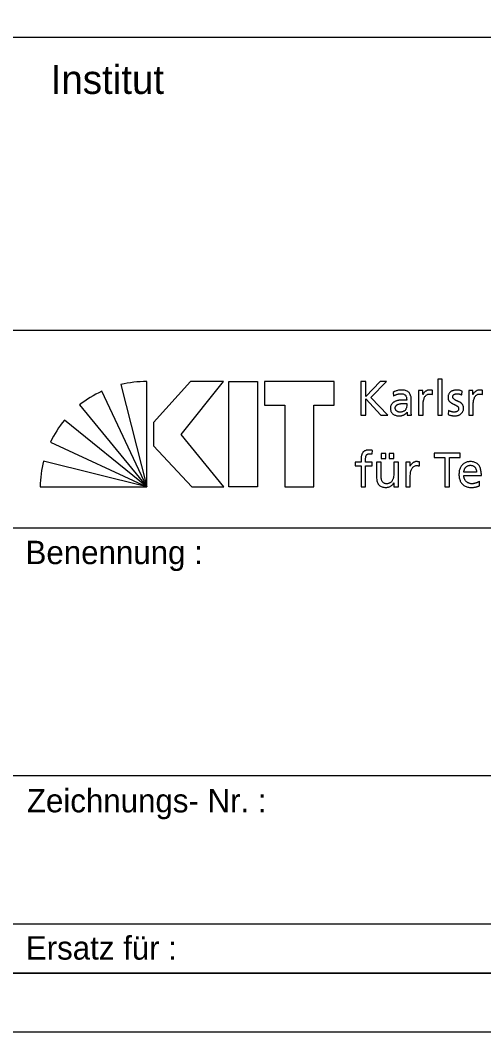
# Model space of a CAD drawing. Extents: x 0 to 841, y 0 to 594.
# Drawn here: x 752.7 to 792.3, y 0 to 86.5 of the extents above; entities that cross this region are included whole.
import ezdxf

# ---------------------------------------------------------------- set-up
doc = ezdxf.new("R2010")
doc.units = 0
doc.layers.add('90_Plankopf', color=7, linetype='Continuous')

msp = doc.modelspace()

# ---------------------------------------------------------------- linework, layer by layer
at = {"layer": '90_Plankopf'}
for p, q in [((836, 84.99), (658.12, 84.99)), ((658.12, 59.99), (836, 59.99)), ((658.12, 59.99), (836, 59.99)), ((763.481, 46.586), (763.481, 55.584)), ((781.81, 55.586), (781.81, 52.706)), ((763.481, 46.586), (759.633, 54.752)), ((761.275, 55.333), (763.481, 46.586)), ((784.579, 54.662), (784.6, 54.332)), ((787.926, 54.484), (787.926, 54.831)), ((790.457, 54.439), (790.49, 54.778)), ((792.211, 54.484), (792.211, 54.831)), ((785.73, 53.709), (785.73, 53.523)), ((786.118, 53.118), (786.118, 53.989)), ((757.744, 53.585), (763.481, 46.586)), ((789.297, 53.118), (789.277, 52.772)), ((763.481, 46.586), (756.434, 52.286)), ((781.81, 52.706), (782.222, 52.706)), ((783.506, 52.706), (784.108, 52.706)), ((755.24, 50.413), (763.481, 46.586)), ((782.773, 49.393), (782.79, 49.706)), ((763.481, 46.586), (754.658, 48.788)), ((786.827, 48.365), (786.827, 48.712)), ((791.706, 47.841), (790.616, 47.841)), ((790.616, 47.552), (792.119, 47.552)), ((791.958, 46.673), (791.958, 47.061)), ((754.364, 46.586), (763.481, 46.586)), ((752.001, 43.07), (836, 43.07)), ((752.001, 21.92), (836, 21.92)), ((752.001, 9.23), (836, 9.23)), ((836, 5), (658.12, 5)), ((669.8, 5), (836, 5)), ((669.8, 5), (836, 5))]:
    msp.add_line(p, q, dxfattribs=at)
for points in [[(0, 0), (841, 0), (841, 594), (0, 594)], [(25, 589), (836, 589), (836, 5), (25, 5)], [(770.066, 55.586), (767.236, 55.586), (764.073, 52.099), (764.073, 50.092), (767.338, 46.586), (770.085, 46.586), (766.422, 51.063)], [(772.97, 55.586), (772.97, 46.586), (770.501, 46.586), (770.501, 55.586)], [(773.562, 55.586), (773.562, 53.56), (775.301, 53.56), (775.301, 46.586), (777.771, 46.586), (777.771, 53.56), (779.51, 53.56), (779.51, 55.586)]]:
    msp.add_lwpolyline(points, close=True, dxfattribs=at)
for points in [[(784.108, 52.706), (782.647, 54.224), (784.001, 55.586), (783.452, 55.586), (782.222, 54.319), (782.222, 55.586), (781.81, 55.586)], [(788.381, 52.706), (788.768, 52.706), (788.768, 55.801), (788.381, 55.801), (788.381, 52.706)], [(787.122, 54.484), (787.113, 54.484), (787.113, 54.81), (786.75, 54.81), (786.75, 52.706), (787.138, 52.706), (787.138, 53.663)], [(791.407, 54.484), (791.398, 54.484), (791.398, 54.81), (791.035, 54.81), (791.035, 52.706), (791.423, 52.706), (791.423, 53.663)], [(782.222, 52.706), (782.222, 54.117), (783.506, 52.706)], [(785.763, 52.978), (785.772, 52.978), (785.772, 52.706), (786.135, 52.706)], [(783.554, 49.426), (783.554, 49.013), (783.942, 49.013), (783.942, 49.426), (783.554, 49.426)], [(784.231, 49.426), (784.231, 49.013), (784.619, 49.013), (784.619, 49.426), (784.231, 49.426)], [(788.99, 46.586), (789.403, 46.586), (789.403, 49.104), (790.298, 49.104), (790.298, 49.467), (788.094, 49.467), (788.094, 49.104), (788.99, 49.104), (788.99, 46.586)], [(781.824, 48.885), (781.824, 48.691), (781.329, 48.691), (781.329, 48.378), (781.824, 48.378), (781.824, 46.586), (782.212, 46.586), (782.212, 48.378), (782.769, 48.378), (782.769, 48.691), (782.212, 48.691), (782.212, 48.918)], [(783.542, 47.602), (783.542, 48.691), (783.154, 48.691), (783.154, 47.441)], [(785.015, 46.586), (785.015, 48.691), (784.627, 48.691), (784.627, 47.717)], [(786.022, 48.365), (786.014, 48.365), (786.014, 48.691), (785.651, 48.691), (785.651, 46.586), (786.039, 46.586), (786.039, 47.544)], [(784.631, 46.921), (784.639, 46.921), (784.639, 46.586), (785.015, 46.586)]]:
    msp.add_lwpolyline(points, dxfattribs=at)
for centre, start, end in [((763.449, 46.056), 89.80527, 103.18947), ((763.662, 46.118), 115.01261, 128.3968), ((763.816, 46.263), 140.78977, 154.17397), ((763.891, 46.438), 165.72225, 179.10644)]:
    msp.add_arc(centre, 9.528, start, end, dxfattribs=at)
for points in [[(786.118, 53.989), (786.119, 54.18), (786.091, 54.341), (786.033, 54.47), (785.975, 54.599), (785.884, 54.696), (785.759, 54.762), (785.635, 54.827), (785.472, 54.86), (785.272, 54.86), (785.138, 54.859), (785.014, 54.841), (784.898, 54.804), (784.782, 54.768), (784.676, 54.721), (784.579, 54.662)], [(784.6, 54.332), (784.653, 54.376), (784.713, 54.414), (784.779, 54.446), (784.846, 54.478), (784.916, 54.503), (784.99, 54.52), (785.063, 54.538), (785.137, 54.546), (785.21, 54.546), (785.339, 54.546), (785.441, 54.526), (785.518, 54.485), (785.594, 54.444), (785.649, 54.383), (785.682, 54.302), (785.715, 54.219), (785.731, 54.118), (785.73, 53.997)], [(787.926, 54.831), (787.899, 54.837), (787.873, 54.841), (787.849, 54.846), (787.824, 54.85), (787.798, 54.854), (787.769, 54.856), (787.741, 54.859), (787.708, 54.86), (787.67, 54.86), (787.595, 54.859), (787.523, 54.843), (787.452, 54.811), (787.382, 54.779), (787.318, 54.736), (787.261, 54.679), (787.203, 54.623), (787.157, 54.558), (787.122, 54.484)], [(787.138, 53.663), (787.139, 53.84), (787.163, 53.993), (787.21, 54.121), (787.257, 54.249), (787.323, 54.348), (787.409, 54.416), (787.494, 54.486), (787.595, 54.521), (787.712, 54.521), (787.746, 54.522), (787.78, 54.519), (787.818, 54.514), (787.855, 54.509), (787.891, 54.499), (787.926, 54.484)], [(790.49, 54.778), (790.414, 54.801), (790.337, 54.82), (790.259, 54.836), (790.181, 54.851), (790.097, 54.859), (790.007, 54.86), (789.903, 54.86), (789.805, 54.847), (789.716, 54.82), (789.625, 54.794), (789.547, 54.753), (789.48, 54.7), (789.412, 54.647), (789.359, 54.579), (789.322, 54.498), (789.284, 54.417), (789.265, 54.321), (789.264, 54.212), (789.265, 54.128), (789.282, 54.056), (789.315, 53.994), (789.347, 53.933), (789.391, 53.88), (789.445, 53.834), (789.5, 53.79), (789.559, 53.75), (789.623, 53.715), (789.688, 53.68), (789.753, 53.647), (789.817, 53.617), (789.882, 53.586), (789.942, 53.555), (789.995, 53.522), (790.05, 53.49), (790.093, 53.454), (790.126, 53.413), (790.158, 53.373), (790.176, 53.325), (790.176, 53.271), (790.176, 53.215), (790.163, 53.167), (790.139, 53.128), (790.116, 53.09), (790.084, 53.059), (790.045, 53.035), (790.006, 53.012), (789.963, 52.995), (789.917, 52.985), (789.871, 52.975), (789.825, 52.97), (789.78, 52.97), (789.742, 52.97), (789.695, 52.975), (789.639, 52.986), (789.584, 52.997), (789.526, 53.014), (789.466, 53.036), (789.405, 53.058), (789.35, 53.085), (789.297, 53.118)], [(789.277, 52.772), (789.366, 52.726), (789.46, 52.694), (789.558, 52.678), (789.656, 52.662), (789.755, 52.655), (789.854, 52.656), (789.949, 52.656), (790.04, 52.669), (790.127, 52.695), (790.215, 52.722), (790.293, 52.762), (790.363, 52.816), (790.431, 52.869), (790.487, 52.938), (790.527, 53.02), (790.568, 53.103), (790.588, 53.2), (790.589, 53.312), (790.588, 53.408), (790.571, 53.489), (790.539, 53.556), (790.506, 53.622), (790.462, 53.679), (790.408, 53.726), (790.354, 53.772), (790.295, 53.811), (790.23, 53.845), (790.165, 53.878), (790.101, 53.909), (790.036, 53.937), (789.971, 53.966), (789.912, 53.995), (789.858, 54.026), (789.804, 54.058), (789.76, 54.095), (789.727, 54.136), (789.695, 54.179), (789.678, 54.23), (789.677, 54.291), (789.678, 54.348), (789.696, 54.396), (789.729, 54.434), (789.763, 54.472), (789.808, 54.5), (789.864, 54.519), (789.92, 54.538), (789.982, 54.546), (790.048, 54.546), (790.072, 54.546), (790.102, 54.543), (790.139, 54.538), (790.175, 54.531), (790.213, 54.523), (790.254, 54.513), (790.295, 54.503), (790.333, 54.491), (790.369, 54.478), (790.405, 54.466), (790.434, 54.453), (790.457, 54.439)], [(792.211, 54.831), (792.184, 54.837), (792.158, 54.841), (792.134, 54.846), (792.11, 54.85), (792.083, 54.854), (792.054, 54.856), (792.026, 54.859), (791.993, 54.86), (791.955, 54.86), (791.88, 54.859), (791.808, 54.843), (791.737, 54.811), (791.667, 54.779), (791.603, 54.736), (791.546, 54.679), (791.488, 54.623), (791.442, 54.558), (791.407, 54.484)], [(791.423, 53.663), (791.424, 53.84), (791.448, 53.993), (791.495, 54.121), (791.542, 54.249), (791.608, 54.348), (791.694, 54.416), (791.779, 54.486), (791.88, 54.521), (791.997, 54.521), (792.03, 54.522), (792.065, 54.519), (792.103, 54.514), (792.14, 54.509), (792.175, 54.499), (792.211, 54.484)], [(785.73, 53.997), (785.68, 54), (785.633, 54.002), (785.589, 54.003), (785.546, 54.004), (785.502, 54.005), (785.459, 54.006), (785.415, 54.006), (785.368, 54.006), (785.318, 54.006), (785.237, 54.006), (785.151, 53.999), (785.063, 53.984), (784.973, 53.97), (784.886, 53.947), (784.801, 53.914), (784.715, 53.881), (784.638, 53.838), (784.569, 53.785), (784.499, 53.731), (784.444, 53.665), (784.403, 53.588), (784.362, 53.509), (784.341, 53.418), (784.34, 53.312), (784.341, 53.16), (784.374, 53.035), (784.439, 52.939), (784.504, 52.842), (784.594, 52.77), (784.71, 52.724), (784.825, 52.679), (784.959, 52.656), (785.111, 52.656), (785.2, 52.657), (785.28, 52.668), (785.35, 52.689), (785.421, 52.709), (785.483, 52.736), (785.536, 52.769), (785.59, 52.802), (785.635, 52.837), (785.673, 52.874), (785.71, 52.911), (785.741, 52.945), (785.763, 52.978)], [(785.73, 53.523), (785.73, 53.418), (785.708, 53.323), (785.664, 53.24), (785.62, 53.157), (785.554, 53.092), (785.467, 53.043), (785.38, 52.995), (785.272, 52.97), (785.144, 52.97), (785.1, 52.97), (785.054, 52.978), (785.008, 52.992), (784.963, 53.007), (784.92, 53.028), (784.882, 53.057), (784.843, 53.087), (784.812, 53.123), (784.789, 53.165), (784.765, 53.207), (784.753, 53.257), (784.752, 53.312), (784.754, 53.386), (784.772, 53.448), (784.808, 53.497), (784.844, 53.546), (784.891, 53.586), (784.949, 53.615), (785.007, 53.645), (785.069, 53.667), (785.135, 53.682), (785.201, 53.696), (785.265, 53.706), (785.326, 53.711), (785.387, 53.715), (785.439, 53.717), (785.483, 53.717), (785.524, 53.717), (785.565, 53.715), (785.607, 53.713), (785.648, 53.711), (785.689, 53.709), (785.73, 53.709)], [(786.135, 52.706), (786.132, 52.726), (786.129, 52.753), (786.126, 52.787), (786.125, 52.821), (786.122, 52.865), (786.121, 52.919), (786.119, 52.973), (786.118, 53.039), (786.118, 53.118)], [(782.79, 49.706), (782.751, 49.712), (782.71, 49.719), (782.668, 49.723), (782.625, 49.728), (782.579, 49.731), (782.53, 49.731), (782.388, 49.73), (782.27, 49.71), (782.178, 49.671), (782.086, 49.631), (782.014, 49.574), (781.962, 49.5), (781.91, 49.426), (781.875, 49.337), (781.854, 49.233), (781.833, 49.129), (781.824, 49.014), (781.824, 48.885)], [(782.212, 48.918), (782.212, 48.99), (782.216, 49.056), (782.224, 49.116), (782.232, 49.177), (782.249, 49.23), (782.275, 49.275), (782.3, 49.32), (782.338, 49.355), (782.388, 49.379), (782.439, 49.404), (782.505, 49.417), (782.588, 49.417), (782.621, 49.417), (782.655, 49.415), (782.688, 49.411), (782.722, 49.407), (782.75, 49.401), (782.773, 49.393)], [(786.827, 48.712), (786.8, 48.717), (786.774, 48.722), (786.75, 48.727), (786.725, 48.731), (786.698, 48.734), (786.67, 48.737), (786.642, 48.739), (786.609, 48.74), (786.571, 48.74), (786.496, 48.74), (786.423, 48.724), (786.352, 48.692), (786.282, 48.66), (786.218, 48.616), (786.161, 48.56), (786.104, 48.503), (786.057, 48.439), (786.022, 48.365)], [(792.119, 47.552), (792.119, 47.722), (792.103, 47.88), (792.072, 48.023), (792.041, 48.168), (791.989, 48.293), (791.918, 48.4), (791.846, 48.507), (791.751, 48.591), (791.631, 48.65), (791.512, 48.709), (791.365, 48.74), (791.19, 48.74), (791.041, 48.74), (790.906, 48.714), (790.785, 48.662), (790.665, 48.61), (790.561, 48.537), (790.474, 48.442), (790.387, 48.347), (790.321, 48.235), (790.275, 48.105), (790.228, 47.976), (790.205, 47.833), (790.204, 47.676), (790.204, 47.504), (790.225, 47.348), (790.269, 47.209), (790.312, 47.069), (790.379, 46.95), (790.469, 46.85), (790.558, 46.749), (790.671, 46.672), (790.808, 46.619), (790.945, 46.564), (791.107, 46.538), (791.293, 46.537), (791.408, 46.538), (791.506, 46.545), (791.587, 46.56), (791.667, 46.575), (791.737, 46.593), (791.797, 46.614), (791.855, 46.634), (791.909, 46.654), (791.958, 46.673)], [(790.616, 47.841), (790.623, 47.91), (790.639, 47.978), (790.664, 48.047), (790.688, 48.116), (790.722, 48.179), (790.768, 48.236), (790.812, 48.294), (790.869, 48.339), (790.937, 48.374), (791.006, 48.408), (791.087, 48.426), (791.182, 48.427), (791.266, 48.426), (791.34, 48.411), (791.404, 48.381), (791.47, 48.35), (791.524, 48.309), (791.569, 48.255), (791.614, 48.201), (791.648, 48.139), (791.671, 48.069), (791.694, 47.998), (791.706, 47.922), (791.706, 47.841)], [(784.627, 47.717), (784.627, 47.589), (784.615, 47.471), (784.589, 47.365), (784.564, 47.26), (784.525, 47.169), (784.473, 47.092), (784.421, 47.015), (784.354, 46.956), (784.273, 46.914), (784.193, 46.872), (784.097, 46.851), (783.987, 46.85), (783.875, 46.857), (783.786, 46.889), (783.721, 46.945), (783.656, 47.002), (783.61, 47.084), (783.582, 47.193), (783.554, 47.302), (783.541, 47.438), (783.542, 47.602)], [(786.039, 47.544), (786.039, 47.721), (786.064, 47.873), (786.11, 48.001), (786.158, 48.129), (786.224, 48.228), (786.31, 48.297), (786.395, 48.367), (786.496, 48.401), (786.612, 48.402), (786.646, 48.403), (786.681, 48.4), (786.718, 48.395), (786.756, 48.389), (786.791, 48.379), (786.827, 48.365)], [(783.154, 47.441), (783.154, 47.251), (783.181, 47.09), (783.237, 46.955), (783.293, 46.82), (783.379, 46.717), (783.496, 46.645), (783.612, 46.574), (783.761, 46.538), (783.942, 46.537), (784.04, 46.538), (784.135, 46.553), (784.225, 46.583), (784.315, 46.614), (784.396, 46.658), (784.466, 46.715), (784.537, 46.772), (784.592, 46.841), (784.631, 46.921)], [(791.958, 47.061), (791.933, 47.041), (791.899, 47.019), (791.852, 46.995), (791.806, 46.971), (791.754, 46.948), (791.694, 46.926), (791.634, 46.904), (791.572, 46.886), (791.506, 46.872), (791.44, 46.858), (791.374, 46.851), (791.309, 46.85), (791.217, 46.851), (791.13, 46.868), (791.046, 46.902), (790.964, 46.935), (790.889, 46.983), (790.825, 47.045), (790.761, 47.107), (790.71, 47.181), (790.673, 47.267), (790.636, 47.353), (790.617, 47.448), (790.616, 47.552)]]:
    msp.add_open_spline(points, degree=3, dxfattribs=at)

# ---------------------------------------------------------------- texts
for s, height, p in [('Institut', 2.464, (755.263, 80.175)), ('Benennung :', 2, (753.113, 39.979)), ('Zeichnungs- Nr. :', 2, (753.227, 18.758)), ('Ersatz für :', 2, (753.139, 6.169))]:
    msp.add_text(s, height=height, dxfattribs=at).set_placement(p)

doc.saveas('drawing.dxf')
